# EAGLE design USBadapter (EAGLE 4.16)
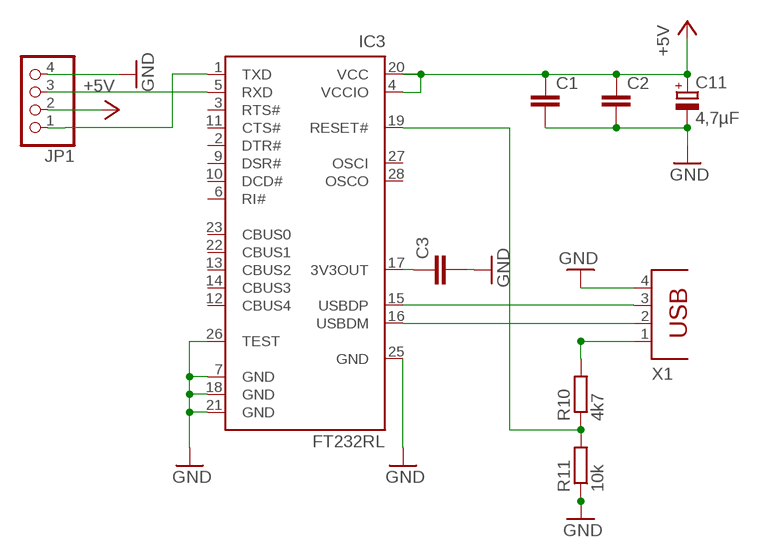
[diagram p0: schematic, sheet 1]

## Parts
C1  C-EUC0805  [C0805]
C2  C-EUC0805  [C0805]
C3  C-EUC0805  [C0805]
C11  4,7µF  CPOL-EUE2.5-5  [E2,5-5]
IC3  FT232RL  [SSOP28]
JP1  PINHD-1X4  [1X04]
R10  4k7  R-EU_0204/2V  [0204V]
R11  10k  R-EU_0204/2V  [0204V]
X1  PN61729  [PN61729]

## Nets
+5V: C1.1 C2.1 C11.+ IC3.4(VCCIO) IC3.20(VCC) JP1.2
GND: C1.2 C2.2 C3.2 C11.- IC3.7(GND) IC3.18(GND) IC3.21(GND) IC3.25(GND) IC3.26(TEST) JP1.4 R11.1 X1.4
N$3: C3.1 IC3.17(3V3OUT)
N$21: IC3.16(USBDM) X1.2
N$28: IC3.15(USBDP) X1.3
N$41: IC3.19(RESET#) R10.1 R11.2
N$42: R10.2 X1.1
RX: IC3.5(RXD) JP1.3
TX: IC3.1(TXD) JP1.1
Unconnected: IC3.2(DTR#) IC3.3(RTS#) IC3.6(RI#) IC3.9(DSR#) IC3.10(DCD#) IC3.11(CTS#) IC3.12(CBUS4) IC3.13(CBUS2) IC3.14(CBUS3) IC3.22(CBUS1) IC3.23(CBUS0) IC3.27(OSCI) IC3.28(OSCO)

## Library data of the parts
C1-C3 = rcl:C-EU: CAPACITOR, European symbol
C11 = rcl:CPOL-EU: POLARIZED CAPACITOR, European symbol
IC3 = ftdichip:FT232R: Source: http://www.ftdichip.com/Documents/DataSheets/DS_FT232R_v104.pdf
JP1 = pinhead:PINHD-1X4: PIN HEADER
R10 R11 = rcl:R-EU_: RESISTOR, European symbol
X1 = con-berg:PN61729: BERG USB connector

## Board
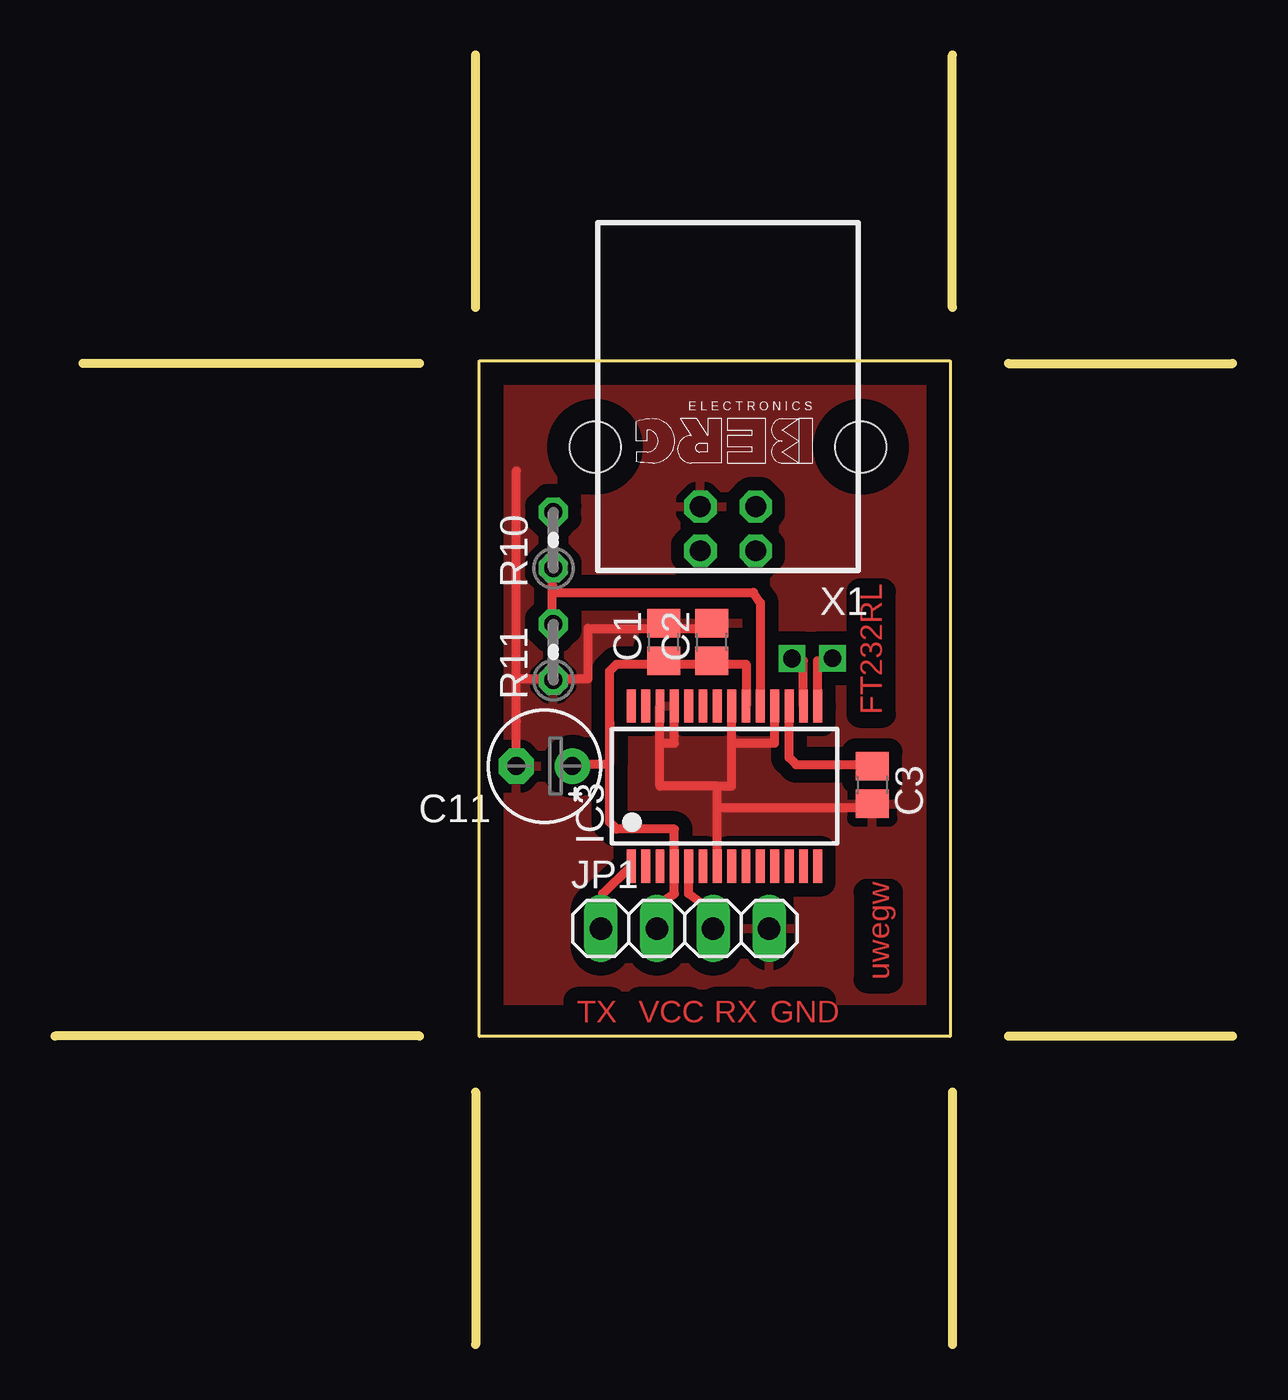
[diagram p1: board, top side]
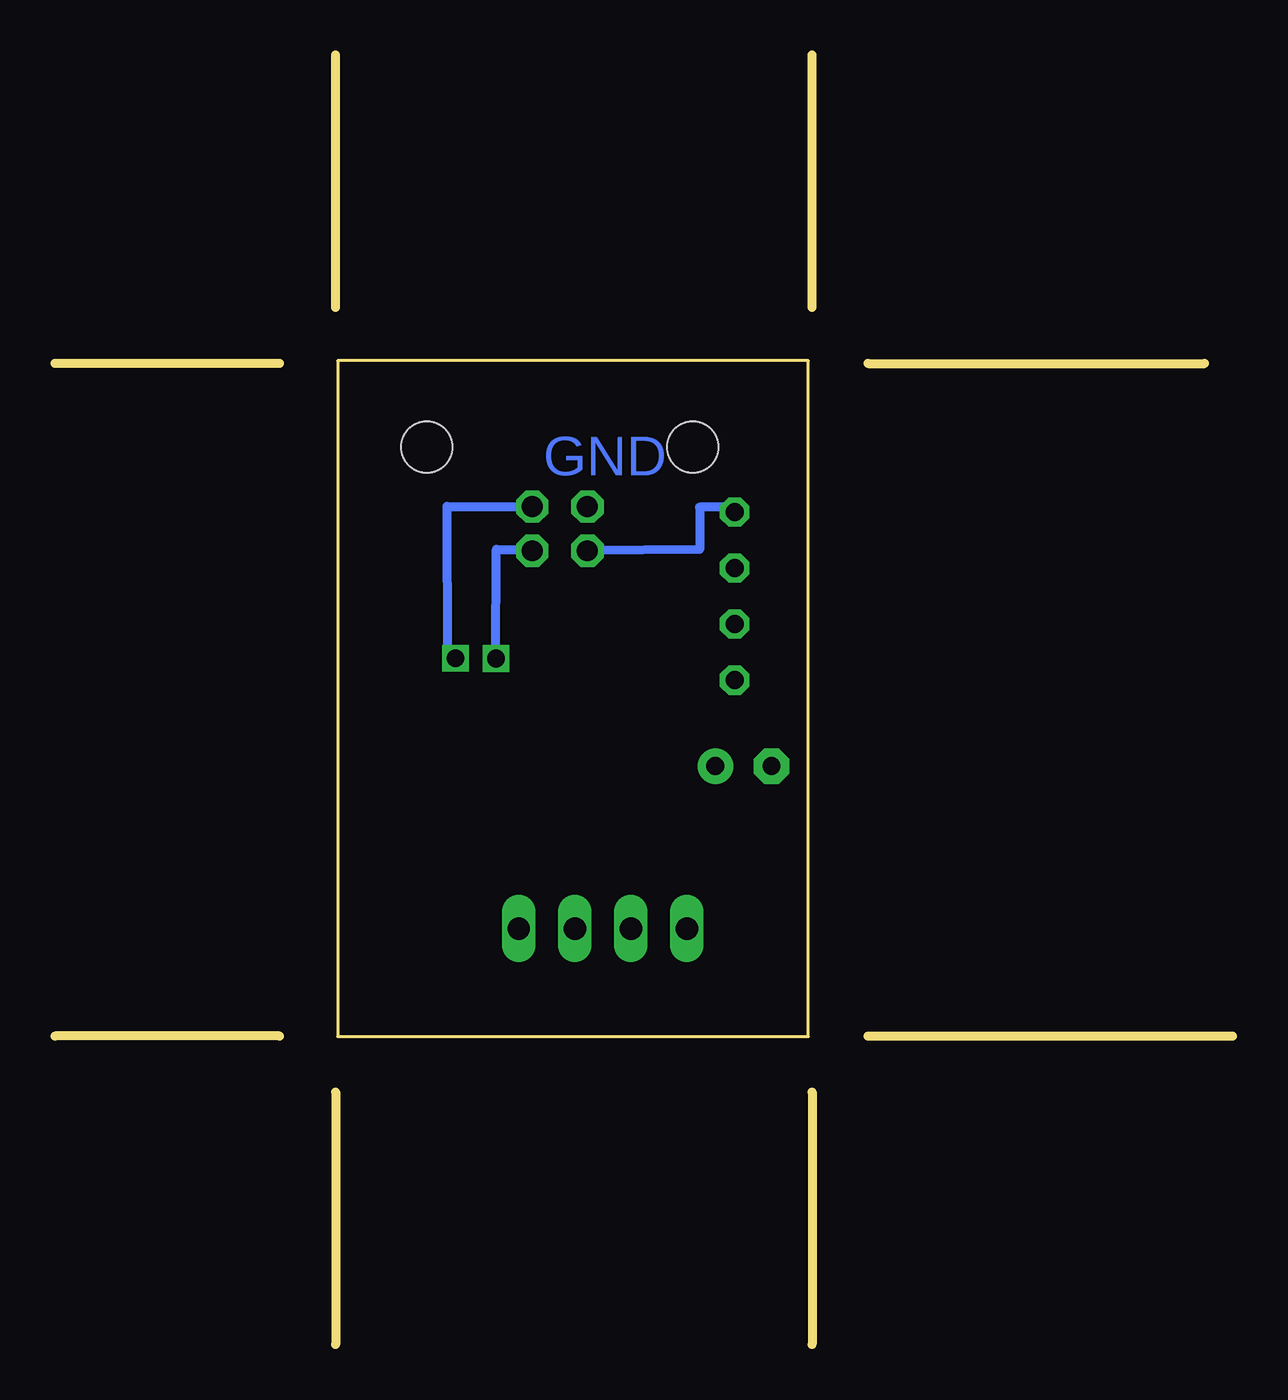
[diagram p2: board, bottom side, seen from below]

Size 53.34 x 58.42 mm. Coordinates in mm from the lower left corner, seen from the top.
Outline: 19.05,11.43 19.05,0
Outline: 40.64,11.43 40.64,0
Outline: 19.05,46.99 19.05,58.42
Outline: 40.64,46.99 40.64,58.42
Outline: 43.18,44.45 53.34,44.45
Outline: 16.51,44.45 1.27,44.45
Outline: 16.51,13.97 0,13.97
Outline: 43.18,13.97 53.34,13.97
Outline: 40.55,13.95 19.22,13.95 19.22,44.57 40.55,44.57 40.55,13.95
Copper layers (1*16): Top 0.035mm / dielectric 1.5mm / Bottom 0.035mm
Design rules "default": minimum track width 10mil, minimum drill 24mil, track to track 8mil, track to pad 8mil, pad to pad 8mil, via to via 8mil, smd to smd 8mil, copper to edge 40mil, drill to drill 8mil, minimum pad ring 10mil, minimum via ring 8mil, stop-mask expansion 4mil, vias tented up to drill 0mil, thermal gap 15mil

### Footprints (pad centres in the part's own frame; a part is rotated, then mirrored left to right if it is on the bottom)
C0805 = smd 1.3 x 1.5: 1 -0.85,0; 2 0.85,0
E2,5-5 = drill 0.813 pad 1.6 round: + -1.27,0 | drill 0.813 pad 1.6 octagon: - 1.27,0
SSOP28 = smd 0.4 x 1.5: 1 -4.225,-3.625; 2 -3.575,-3.625; 3 -2.925,-3.625; 4 -2.275,-3.625; 5 -1.625,-3.625; 6 -0.975,-3.625; 7 -0.325,-3.625; 8 0.325,-3.625; 9 0.975,-3.625; 10 1.625,-3.625; 11 2.275,-3.625; 12 2.925,-3.625; 13 3.575,-3.625; 14 4.225,-3.625; 15 4.225,3.625; 16 3.575,3.625; 17 2.925,3.625; 18 2.275,3.625; 19 1.625,3.625; 20 0.975,3.625; 21 0.325,3.625; 22 -0.325,3.625; 23 -0.975,3.625; 24 -1.625,3.625; 25 -2.275,3.625; 26 -2.925,3.625; 27 -3.575,3.625; 28 -4.225,3.625
1X04 = drill 1.016 long: 1 -3.81,0; 2 -1.27,0; 3 1.27,0; 4 3.81,0
0204V = drill 0.813 octagon: 1 -1.27,0; 2 1.27,0
PN61729 = drill 0.95 octagon: 1 1.25,4.71; 2 -1.25,4.71; 3 -1.25,2.71; 4 1.25,2.71 | hole 2.3: -6.02,0; 6.02,0

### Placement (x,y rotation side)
C1  27.56,31.83 90 top
C2  29.74,31.83 90 top
C3  37.02,25.34 270 top
C11  22.16,26.2 180 top
IC3  30.32,25.29 0 top
JP1  28.53,18.84 0 top
R10  22.56,36.45 90 top
R11  22.56,31.37 90 top
X1  30.48,40.67 180 top

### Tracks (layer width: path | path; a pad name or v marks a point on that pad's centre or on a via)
+5V
  Top 0.406: IC3.20 31.3,30.82 29.99,30.82 | 29.99,30.82 C2.1 | C1.1 27.72,30.82 28.05,30.82 | 28.05,30.82 29.99,30.82 | 25.12,28.22 25.12,23.66 25.44,23.34 28.05,23.34 IC3.4 28.05,20.42 27.07,19.77 27.39,18.8 JP1.2 | 25.12,28.22 25.12,30.5 25.44,30.82 28.05,30.82 | 25.12,28.22 25.12,26.27 23.49,26.27 C11.+
GND
  Top 0.406: IC3.7 29.99,24.32 | 29.99,24.32 29.99,25.3 | 29.99,25.3 30.64,25.3 30.64,27.24 | IC3.21 30.64,27.24 | IC3.18 32.59,27.24 30.64,27.24 | IC3.26 27.39,27.24 | 27.39,27.24 27.39,25.3 29.99,25.3 | 28.05,27.57 28.05,27.24 27.39,27.24 | 28.05,27.57 28.05,27.92 | 29.99,24.32 36.82,24.32 36.82,24.49 C3.2 37.14,24.32 | 27.72,32.45 C1.2 | C2.2 29.67,32.45 27.72,32.45 | 20.89,30.17 22.52,30.17 | 20.89,30.17 20.89,39.59 | 27.72,32.45 24.14,32.45 24.14,30.17 22.52,30.17 | 22.52,30.17 R11.1 | C11.- 20.89,28.22 20.89,30.17 | 28.05,27.57 | 28.05,27.57 IC3.25
  pour Top (isolate 0.61): 20.22,43.57 39.55,43.57 39.55,15.57 20.22,15.57
N$3
  Top 0.406: IC3.17 33.24,26.59 33.56,26.27 36.82,26.27 36.82,26.2 C3.1
N$21  (via drill 0.8)
  Top 0.406: 33.37,30.99 33.27,30.99 | 33.37,30.99 v33.37,31.08 | IC3.16 33.9,30.99 33.37,30.99
  Bottom 0.406: v33.37,31.08 33.36,36.02 31.62,36.02 X1.2
N$28  (via drill 0.8)
  Top 0.406: IC3.15 34.55,28.87 34.55,30.99 34.54,30.99 | 34.54,30.99 34.54,30.48 | v35.21,31.1 35.21,30.99 34.54,30.99
  Bottom 0.406: v35.21,31.1 35.56,31.1 35.59,37.97 31.62,37.97 | 31.62,37.97 | 31.62,37.97 X1.3
N$41
  Top 0.406: IC3.19 31.95,33.6 31.63,34.07 22.52,34.07 22.52,34.4 | 22.52,34.4 22.52,34.72 R10.1 22.52,34.4 | R11.2 22.52,32.45 22.52,34.4
N$42
  Bottom 0.406: X1.1 24.14,36.02 24.14,37.94 22.52,37.94 R10.2
RX
  Top 0.406: IC3.5 28.7,20.42 29.99,19.45 29.67,18.8 JP1.3
TX
  Top 0.406: IC3.1 24.8,20.42 24.8,18.8 JP1.1

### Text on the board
Top: FT232RL | uwegw | TX | VCC | RX | GND
Bottom: GND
